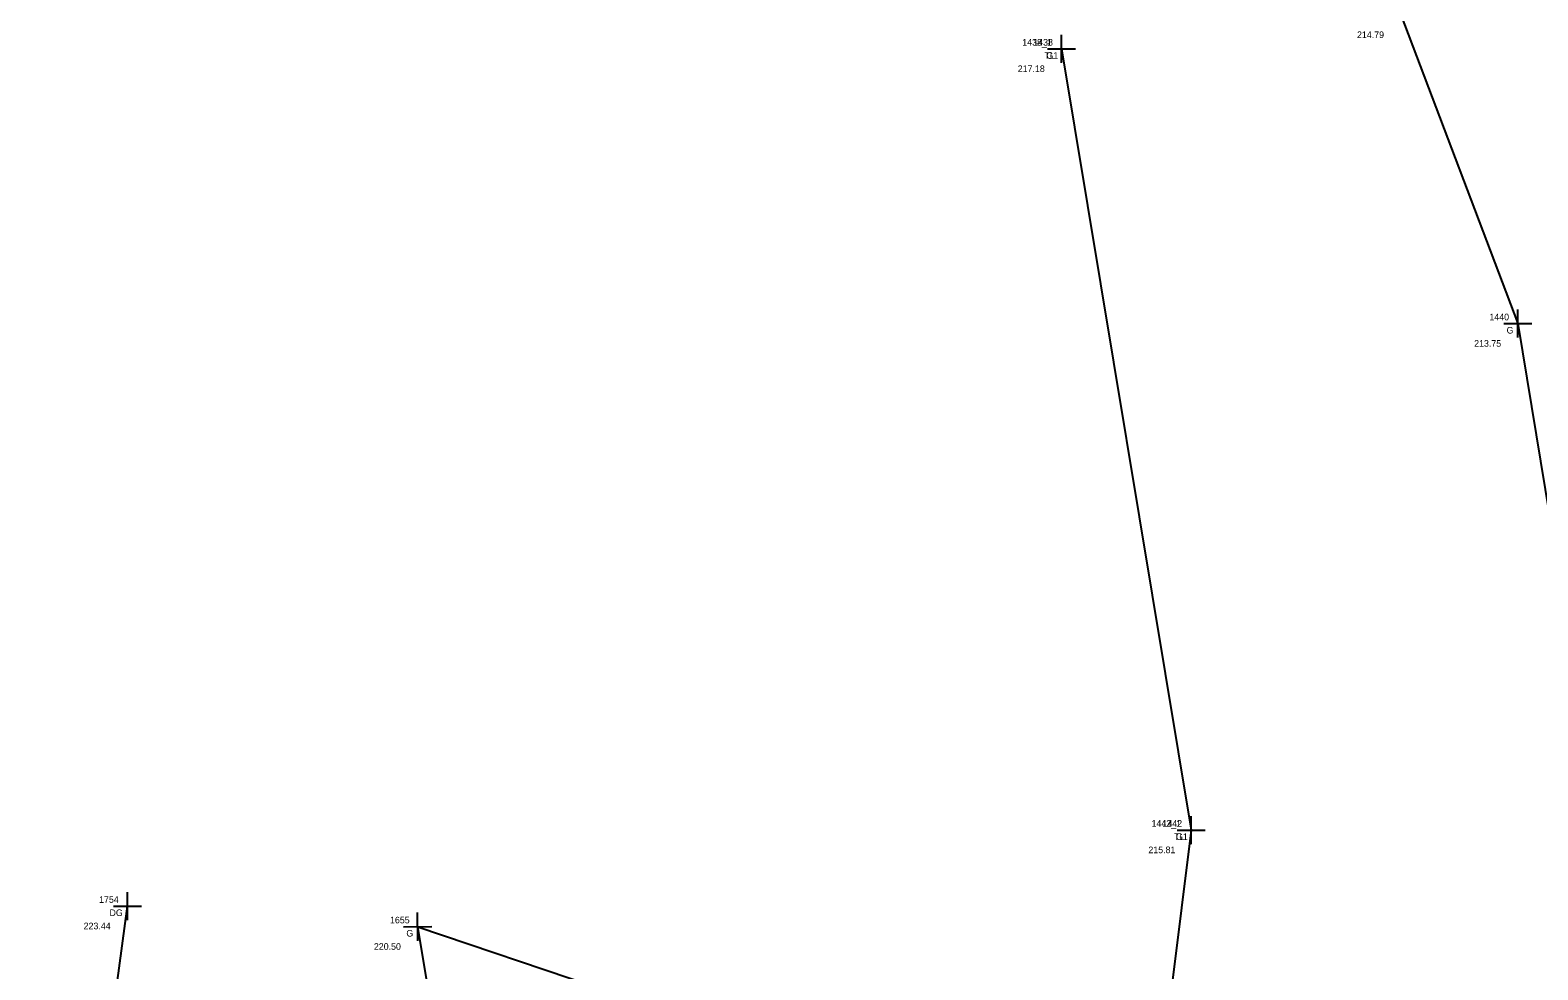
# Model space of a CAD drawing. Extents: x 1158983 to 1160032, y 610902 to 611573.
# Drawn here: x 1159273.7 to 1159342.2, y 611349.6 to 611392.3 of the extents above; entities that cross this region are included whole.
import ezdxf

# ---------------------------------------------------------------- set-up
doc = ezdxf.new("R2010")
doc.units = 0
for name, color, linetype in [('S_Field_Code', 7, 'Continuous'), ('S_Ground_Elevation', 7, 'Continuous'), ('S_Point_Elevation', 7, 'Continuous'), ('S_Point_Name', 7, 'Continuous'), ('S_Roadway_Drive_Gravel', 7, 'Continuous'), ('S_Survey_Shot', 7, 'Continuous'), ('S_Trees_TreeLine', 7, 'Continuous')]:
    doc.layers.add(name, color=color, linetype=linetype)

msp = doc.modelspace()

# ---------------------------------------------------------------- linework, layer by layer
at = {"layer": 'S_Ground_Elevation'}
for points in [[(1159366.84, 611572.506), (1159350.471, 611523.657), (1159338.484, 611491.874), (1159327.308, 611461.853), (1159319.303, 611430.663), (1159324.274, 611410.669), (1159335.989, 611392.955), (1159341.308, 611378.939), (1159344.811, 611357.612), (1159350.212, 611325.577), (1159356.223, 611311.934), (1159358.143, 611294.408), (1159357.674, 611289.159), (1159344.861, 611293.167), (1159338.584, 611293.952), (1159337.254, 611299.39), (1159348.329, 611299.371), (1159356.747, 611302.3)], [(1159320.582, 611391.413), (1159326.464, 611355.944), (1159322.505, 611324.086)], [(1159352.149, 611311.344), (1159339.531, 611314.728), (1159324.665, 611314.427), (1159313.821, 611316.237), (1159300.045, 611315.663), (1159295.131, 611328.971), (1159291.342, 611351.557), (1159307.492, 611346.1), (1159310.1, 611324.165)]]:
    msp.add_lwpolyline(points, dxfattribs=at)
at = {"layer": 'S_Roadway_Drive_Gravel'}
msp.add_lwpolyline([(1159275.665, 611310.381), (1159273.743, 611319.611), (1159278.161, 611352.489)], dxfattribs=at)
at = {"layer": 'S_Survey_Shot'}
for p, q in [((1159320.583, 611390.776), (1159320.58, 611392.049)), ((1159320.583, 611390.776), (1159320.58, 611392.049)), ((1159319.945, 611391.411), (1159321.218, 611391.414)), ((1159319.945, 611391.411), (1159321.218, 611391.414)), ((1159320.582, 611391.413), (1159320.582, 611391.413)), ((1159320.582, 611391.413), (1159320.582, 611391.413)), ((1159341.309, 611378.303), (1159341.306, 611379.575)), ((1159340.671, 611378.938), (1159341.944, 611378.94)), ((1159341.308, 611378.939), (1159341.308, 611378.939)), ((1159326.466, 611355.308), (1159326.463, 611356.58)), ((1159326.466, 611355.308), (1159326.463, 611356.58)), ((1159325.828, 611355.943), (1159327.101, 611355.945)), ((1159325.828, 611355.943), (1159327.101, 611355.945)), ((1159326.464, 611355.944), (1159326.464, 611355.944)), ((1159326.464, 611355.944), (1159326.464, 611355.944)), ((1159277.525, 611352.488), (1159278.797, 611352.491)), ((1159278.163, 611351.853), (1159278.16, 611353.126)), ((1159278.161, 611352.489), (1159278.161, 611352.489)), ((1159291.343, 611350.92), (1159291.34, 611352.193)), ((1159290.705, 611351.555), (1159291.978, 611351.558)), ((1159291.342, 611351.557), (1159291.342, 611351.557))]:
    msp.add_line(p, q, dxfattribs=at)
at = {"layer": 'S_Trees_TreeLine'}
msp.add_lwpolyline([(1159320.582, 611391.413), (1159326.464, 611355.944), (1159322.505, 611324.086)], dxfattribs=at)

# ---------------------------------------------------------------- texts
at = {"layer": 'S_Field_Code'}
for s, p in [('TL', (1159319.809, 611390.963)), ('G1', (1159319.897, 611390.963)), ('G', (1159340.793, 611378.489)), ('TL', (1159325.692, 611355.494)), ('G1', (1159325.779, 611355.494)), ('DG', (1159277.346, 611352.039)), ('G', (1159290.827, 611351.107))]:
    msp.add_text(s, height=0.3, dxfattribs=at).set_placement(p)
at = {"layer": 'S_Point_Elevation'}
for s, p in [('214.79', (1159334, 611391.905)), ('217.18', (1159318.593, 611390.363)), ('217.18', (1159318.593, 611390.363)), ('213.75', (1159339.319, 611377.889)), ('215.81', (1159324.525, 611354.894)), ('215.81', (1159324.525, 611354.894)), ('223.44', (1159276.172, 611351.439)), ('220.50', (1159289.353, 611350.507))]:
    msp.add_text(s, height=0.3, dxfattribs=at).set_placement(p)
at = {"layer": 'S_Point_Name'}
for s, p in [('1438_1', (1159318.798, 611391.563)), ('1438', (1159319.297, 611391.563)), ('1440', (1159340.011, 611379.089)), ('1442_1', (1159324.667, 611356.094)), ('1442', (1159325.165, 611356.094)), ('1754', (1159276.874, 611352.639)), ('1655', (1159290.085, 611351.707))]:
    msp.add_text(s, height=0.3, dxfattribs=at).set_placement(p)

doc.saveas('drawing.dxf')
